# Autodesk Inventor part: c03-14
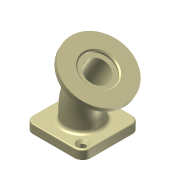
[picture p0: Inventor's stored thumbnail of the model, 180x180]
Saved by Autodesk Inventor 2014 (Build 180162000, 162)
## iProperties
Created: 2011-11
Part Number: c03-14
Material: Iron, Cast
Document SubType Name: Modeling
Designer: Thom Tremblay
Density: 7.25 g/cm^3
Mass: 1087.5 g
Surface Area: 260 cm^2
Volume: 150 cm^3
Appearance: Nylon 6
Author: Thom Tremblay
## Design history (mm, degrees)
sketch "Sketch1"
  geometry: L1 (50, -50)-(-50, -50); L2 (-50, -50)-(-50, 50); L3 (-50, 50)-(50, 50); L4 (50, 50)-(50, -50); C1 r 20 at (0, 0); C2 r 30 at (0, 0); 3 further points
  constraints: 8 end point, 2 centre point, 2 coincident, 2 midpoint, 2 parallel, 2 perpendicular, 1 horizontal, 1 horizontal alignment, 1 vertical alignment
  dimensions: "d0" = 100 distance of L2.end L3.end; "d3" = 40 diameter of C1; "d4" = 10 radial gap between concentric circles of C2 C1
extrude "Extrusion1" new body sketch "Sketch1" distance "d1" = 15; taper "d2" = 0 deg
sketch "Sketch2"
  geometry: L1 (0, 0)-(0, 30); L2 (12.794, 77.746)-(27.794, 103.727); A1 r 95.493 centre (95.493, 30) between (12.794, 77.746) and (0, 30)
  constraints: 4 end point, 2 point on circle, 2 tangent, 1 centre point, 1 vertical
  dimensions: "d5" = 30 distance of L1.start L1.end; "d7" = 50 dimension on A1; "d9" = 30 distance of L2.start L2.end; "d10" = 30 deg angle of L2 L1
sketch "Sketch3"
  geometry: L1 (12.794, 77.746)-(27.794, 103.727) reference; L2 (27.794, 103.727)-(75.425, 76.227); L3 (75.425, 76.227)-(70.425, 67.567); L4 (70.425, 67.567)-(22.794, 95.067); L5 (22.794, 95.067)-(27.794, 103.727); 2 further points
  constraints: 8 end point, 2 parallel, 2 perpendicular
  dimensions: "d11" = 110 diameter of L3 L5; "d13" = 10 distance between parallel lines of L2 L4
revolve "Revolution1" sketch "Sketch3" stored, may be unused: angle "d14" = 90 deg
sweep "Sweep1" dims "d15" = 0
sweep "Sweep2" dims "d16" = 0
sketch "Sketch4"
  geometry: C1 r 55 at (0, 0) reference; C2 r 27.5 at (0, 0); 1 further point
  constraints: 1 centre point, 1 coincident
  dimensions: "d17" = 55 diameter of C2
extrude "Extrusion2" cut sketch "Sketch4" distance "d18" = 5; taper "d19" = 0 deg
fillet "Fillet1" dims "d20" = 14
fillet "Fillet2" dims "d21" = 6, "d22" = 2
chamfer "Chamfer1" distance "d23" = 2; stored, may be unused: second distance "d24" = 2, angle "d25" = 45 deg
chamfer "Chamfer2" distance "d26" = 2; stored, may be unused: second distance "d27" = 4, angle "d28" = 45 deg
hole "Hole1" diameter "d31" = 10; stored, may be unused: countersink angle "d35" = 90 deg, drill point angle "d37" = 118 deg; dims "d29" = 30, "d30" = 10, "d32" = 6, "d33" = 4, "d34" = 2, "d36" = 8
hole "Hole2" diameter "d40" = 11; stored, may be unused: countersink angle "d44" = 90 deg, drill point angle "d46" = 118 deg; dims "d38" = 10, "d39" = 10, "d41" = 6, "d42" = 20, "d43" = 2, "d45" = 8
body "Solid1"
